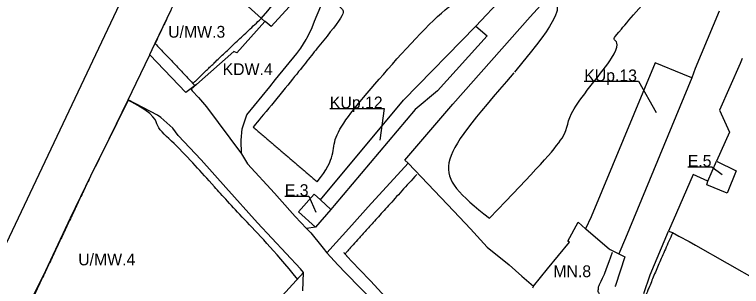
# Model space of a CAD drawing. Extents: x 7424788 to 7425732, y 5549810 to 5550591.
# Drawn here: x 7425037.8 to 7425283.7, y 5550184.4 to 5550276.4 of the extents above; entities that cross this region are included whole.
import ezdxf

# ---------------------------------------------------------------- set-up
doc = ezdxf.new("R2010")
doc.units = 0
for name, color, linetype in [('WIL_granica obszaru objętego planem', 7, 'Continuous'), ('WIL_linia rozgraniczające tereny o różnym przeznaczeniu lub różnych zasadach zagospodarowania', 7, 'Continuous'), ('WIL_linia rozgraniczające tereny o różnym przeznaczeniu lub różnych zasadach zagospodarowania_OPISY', 7, 'Continuous'), ('WIL_nieprzekraczalne linie zabudowy', 7, 'Continuous')]:
    doc.layers.add(name, color=color, linetype=linetype)

msp = doc.modelspace()

# ---------------------------------------------------------------- linework, layer by layer
at = {"layer": 'WIL_granica obszaru objętego planem'}
msp.add_line((7424904.13, 5549923.06), (7425177.26, 5550499.06), dxfattribs=at)
at = {"layer": 'WIL_linia rozgraniczające tereny o różnym przeznaczeniu lub różnych zasadach zagospodarowania'}
for p, q in [((7424904.13, 5549923.06), (7425177.26, 5550499.06)), ((7425098.81, 5550295.36), (7425122.45, 5550274.11)), ((7425207.15, 5550286.68), (7425193.88, 5550272.5)), ((7425212.23, 5550275.61), (7425222.6, 5550287.16)), ((7425139.33, 5550274.15), (7425143.17, 5550283.36)), ((7425131.92, 5550280.39), (7425124.63, 5550272.37)), ((7425085.37, 5550266.74), (7425090.81, 5550278.06)), ((7425186.06, 5550246.06), (7425212.23, 5550275.61)), ((7425276.2, 5550277.52), (7425268.06, 5550258.13)), ((7425122.45, 5550274.11), (7425112.96, 5550263.43)), ((7425122.55, 5550274.02), (7425122.45, 5550274.11)), ((7425124.63, 5550272.37), (7425122.55, 5550274.02)), ((7425138.53, 5550272), (7425139.33, 5550274.15)), ((7425137.5, 5550269.94), (7425138.53, 5550272)), ((7425169.4, 5550247.49), (7425193.88, 5550272.5)), ((7425193.88, 5550272.5), (7425197.67, 5550269.22)), ((7425136.49, 5550268.02), (7425136.73, 5550268.48)), ((7425136.73, 5550268.48), (7425137.5, 5550269.94)), ((7425197.67, 5550269.22), (7425180.93, 5550250.6)), ((7425084.35, 5550264.57), (7425085.37, 5550266.74)), ((7425134.67, 5550265.1), (7425136.49, 5550268.02)), ((7425083.55, 5550262.87), (7425084.35, 5550264.57)), ((7425112, 5550263.95), (7425099.35, 5550252.8)), ((7425112.96, 5550263.43), (7425112, 5550263.95)), ((7425126.12, 5550254.43), (7425133.32, 5550263.28)), ((7425133.32, 5550263.28), (7425134.67, 5550265.1)), ((7425078.96, 5550253.17), (7425083.53, 5550262.83)), ((7425083.53, 5550262.83), (7425083.55, 5550262.87)), ((7425095.8, 5550250.1), (7425083.53, 5550262.83)), ((7425283.97, 5550261.56), (7425283.22, 5550259.84)), ((7425254.57, 5550260.03), (7425232.9, 5550208.02)), ((7425263.83, 5550256.24), (7425254.57, 5550260.03)), ((7425283.22, 5550259.84), (7425276.33, 5550244.06)), ((7425266.93, 5550255.04), (7425263.83, 5550256.24)), ((7425268.06, 5550258.13), (7425266.93, 5550255.04)), ((7425124.16, 5550251.97), (7425126.12, 5550254.43)), ((7425266.93, 5550255.04), (7425244.43, 5550200.77)), ((7425076.29, 5550247.54), (7425078.96, 5550253.17)), ((7425099.35, 5550252.8), (7425095.8, 5550250.1)), ((7425099.35, 5550252.8), (7425097.5, 5550251.18)), ((7425097.5, 5550251.18), (7425097.89, 5550250.66)), ((7425116.4, 5550242.44), (7425124.16, 5550251.97)), ((7425097.89, 5550250.66), (7425100.07, 5550248.32)), ((7425180.93, 5550250.6), (7425173.38, 5550244.35)), ((7425070.29, 5550235.33), (7425076.29, 5550247.54)), ((7425086.15, 5550242.34), (7425076.29, 5550247.54)), ((7425100.07, 5550248.32), (7425102.77, 5550245.19)), ((7425141.27, 5550213.74), (7425169.4, 5550247.49)), ((7425169.89, 5550227.21), (7425186.06, 5550246.06)), ((7425102.77, 5550245.19), (7425114.57, 5550229.26)), ((7425173.38, 5550244.35), (7425145.91, 5550211.81)), ((7425276.33, 5550244.06), (7425279.7, 5550236.65)), ((7425087.31, 5550241.55), (7425086.15, 5550242.34)), ((7425091.4, 5550237.96), (7425087.31, 5550241.55)), ((7425114.85, 5550237.79), (7425116.4, 5550242.44)), ((7425093.12, 5550235.5), (7425091.4, 5550237.96)), ((7425114.43, 5550233.96), (7425114.85, 5550237.79)), ((7425279.7, 5550236.65), (7425275.3, 5550226.79)), ((7425063.61, 5550221.83), (7425070.29, 5550235.33)), ((7425100.91, 5550227.29), (7425093.12, 5550235.5)), ((7425114.57, 5550229.26), (7425114.43, 5550233.96)), ((7425114.57, 5550229.26), (7425116.63, 5550225.93)), ((7425109.28, 5550217.86), (7425100.91, 5550227.29)), ((7425170.93, 5550226.16), (7425169.89, 5550227.21)), ((7425272.35, 5550220.04), (7425275.3, 5550226.79)), ((7425275.3, 5550226.79), (7425281.93, 5550223.6)), ((7425116.63, 5550225.93), (7425125.76, 5550215.95)), ((7425157.45, 5550211.34), (7425170.93, 5550226.16)), ((7425170.93, 5550226.16), (7425173.25, 5550223.73)), ((7425056.69, 5550207.65), (7425063.61, 5550221.83)), ((7425173.25, 5550223.73), (7425186.39, 5550209.91)), ((7425267.41, 5550222.26), (7425261.72, 5550209.31)), ((7425272.35, 5550220.04), (7425267.41, 5550222.26)), ((7425281.93, 5550223.6), (7425278.86, 5550215.96)), ((7425272, 5550218.8), (7425272.35, 5550220.04)), ((7425119.99, 5550206), (7425109.28, 5550217.86)), ((7425278.86, 5550215.96), (7425272, 5550218.8)), ((7425125.76, 5550215.95), (7425127.48, 5550214.08)), ((7425127.48, 5550214.08), (7425132.77, 5550208.11)), ((7425133.82, 5550209.65), (7425139.14, 5550215.71)), ((7425139.14, 5550215.71), (7425141.27, 5550213.74)), ((7425141.27, 5550213.74), (7425144.83, 5550210.45)), ((7425145.91, 5550211.81), (7425144.83, 5550210.45)), ((7425139.56, 5550204.5), (7425133.82, 5550209.65)), ((7425144.83, 5550210.45), (7425139.56, 5550204.5)), ((7425151.95, 5550205.16), (7425157.45, 5550211.34)), ((7425186.39, 5550209.91), (7425192.1, 5550203.98)), ((7425261.72, 5550209.31), (7425259.03, 5550203.19)), ((7425048.44, 5550189.85), (7425056.69, 5550207.65)), ((7425132.77, 5550208.11), (7425136.57, 5550204.08)), ((7425232.9, 5550208.02), (7425231, 5550203.98)), ((7425134.56, 5550190.36), (7425119.99, 5550206)), ((7425139.56, 5550204.5), (7425136.57, 5550204.08)), ((7425143.48, 5550195.76), (7425151.95, 5550205.16)), ((7425224.99, 5550199.72), (7425228.42, 5550206.21)), ((7425228.42, 5550206.21), (7425231, 5550203.98)), ((7425136.57, 5550204.08), (7425138.04, 5550202.52)), ((7425138.04, 5550202.52), (7425139.41, 5550200.83)), ((7425192.1, 5550203.98), (7425197.68, 5550197.68)), ((7425231, 5550203.98), (7425231.16, 5550203.84)), ((7425231.16, 5550203.84), (7425238.93, 5550197.13)), ((7425252.87, 5550188.4), (7425259.03, 5550203.19)), ((7425259.03, 5550203.19), (7425260.41, 5550202.68)), ((7425260.41, 5550202.68), (7425262.56, 5550201.5)), ((7425139.41, 5550200.83), (7425140.39, 5550199.61)), ((7425140.39, 5550199.61), (7425142.22, 5550197.34)), ((7425218.1, 5550190.41), (7425225.55, 5550199.42)), ((7425225.55, 5550199.42), (7425224.99, 5550199.72)), ((7425244.43, 5550200.77), (7425242.23, 5550195.47)), ((7425262.56, 5550201.5), (7425266.02, 5550199.6)), ((7425266.02, 5550199.6), (7425268.19, 5550198.41)), ((7425142.22, 5550197.34), (7425143.48, 5550195.76)), ((7425197.68, 5550197.68), (7425205.12, 5550191.74)), ((7425238.93, 5550197.13), (7425239.3, 5550196.94)), ((7425239.3, 5550196.94), (7425242.23, 5550195.47)), ((7425268.19, 5550198.41), (7425291.09, 5550185.38)), ((7425147.25, 5550191.66), (7425143.48, 5550195.76)), ((7425244.29, 5550194.44), (7425241.1, 5550184.72)), ((7425242.23, 5550195.47), (7425244.29, 5550194.44)), ((7425044.09, 5550181.16), (7425048.44, 5550189.85)), ((7425135.52, 5550189.18), (7425134.56, 5550190.36)), ((7425149.73, 5550189.09), (7425147.25, 5550191.66)), ((7425205.12, 5550191.74), (7425209.45, 5550187.89)), ((7425213.33, 5550184.48), (7425218.1, 5550190.41)), ((7425135.52, 5550189.18), (7425122.11, 5550174.46)), ((7425135.34, 5550182.92), (7425135.52, 5550189.18)), ((7425163.53, 5550175.09), (7425149.73, 5550189.09)), ((7425209.45, 5550187.89), (7425213.33, 5550184.48)), ((7425250.74, 5550182.05), (7425252.87, 5550188.4)), ((7425213.33, 5550184.48), (7425213, 5550183.82)), ((7425241.1, 5550184.72), (7425240.93, 5550184.38))]:
    msp.add_line(p, q, dxfattribs=at)
at = {"layer": 'WIL_linia rozgraniczające tereny o różnym przeznaczeniu lub różnych zasadach zagospodarowania_OPISY'}
for points in [[(7425230.52, 5550253.83), (7425248.9, 5550253.83), (7425254.87, 5550243.27)], [(7425144.47, 5550244.67), (7425162.81, 5550244.67), (7425161.36, 5550233.91)], [(7425265.55, 5550224.94), (7425273.72, 5550224.94), (7425277.14, 5550222.31)], [(7425129.23, 5550215.01), (7425137.36, 5550215.01), (7425139.7, 5550209.52)]]:
    msp.add_lwpolyline(points, dxfattribs=at)
at = {"layer": 'WIL_nieprzekraczalne linie zabudowy'}
for points, degree in [([(7425198.43, 5550207.48), (7425214.24, 5550223.9), (7425226.81, 5550237.4), (7425222.97, 5550241.17), (7425243.74, 5550265.11), (7425240.43, 5550268.16), (7425240.3, 5550268.42), (7425256.84, 5550287.34), (7425277.61, 5550312.54), (7425279.73, 5550311.22), (7425289.78, 5550323.65), (7425286.52, 5550326.6), (7425303.41, 5550346.01), (7425314.85, 5550359.25), (7425313.06, 5550361.03), (7425321.13, 5550371.48), (7425305.65, 5550384.84), (7425294.14, 5550370.95), (7425269.41, 5550342.11), (7425267.03, 5550339.06), (7425265.3, 5550337.01), (7425268.22, 5550334.57), (7425251.81, 5550317.24), (7425232.23, 5550295.28), (7425230.78, 5550292.96), (7425222.05, 5550283.57), (7425219.8, 5550280.13), (7425223.37, 5550276.56), (7425206.92, 5550256.89)], 3), ([(7425140.2, 5550219.85), (7425146.9, 5550228.14), (7425142.94, 5550232.9), (7425158.81, 5550252.21), (7425188.63, 5550285.42), (7425194.4, 5550279.73), (7425203.66, 5550289.65), (7425178.12, 5550312.94), (7425165.03, 5550300.63), (7425159.87, 5550304.6), (7425158.81, 5550305.13), (7425149.95, 5550294.28), (7425149.02, 5550293.23), (7425152.46, 5550289.65), (7425145.32, 5550281.19), (7425148.49, 5550278.41), (7425150.08, 5550277.09), (7425139.5, 5550264.25), (7425133.28, 5550256.18), (7425120.18, 5550240.31), (7425118.49, 5550238.35)], 3), ([(7425121.21, 5550275.03), (7425134.5, 5550289.72), (7425124.58, 5550298.69), (7425121.07, 5550301.98), (7425119.26, 5550299.82)], 3), ([(7425098.84, 5550295.15), (7425085.37, 5550266.65)], 1), ([(7425098.08, 5550253.07), (7425107.05, 5550261.76), (7425121.21, 5550275.03)], 2), ([(7425085.37, 5550266.65), (7425098.88, 5550252.32)], 1), ([(7425206.73, 5550256.69), (7425179.32, 5550224.96), (7425178.26, 5550223.77), (7425198.43, 5550207.48)], 3), ([(7425076.25, 5550247.42), (7425063.48, 5550221.69)], 1), ([(7425076.25, 5550247.42), (7425076.27, 5550247.41)], 1), ([(7425133.61, 5550186.84), (7425125.39, 5550196.96), (7425114.54, 5550207.96), (7425104.72, 5550218.96), (7425099.29, 5550224.97), (7425091.67, 5550233.18), (7425084.77, 5550238.9), (7425086.09, 5550242.27), (7425076.25, 5550247.42)], 3), ([(7425118.49, 5550238.35), (7425140.2, 5550219.85)], 1), ([(7425063.48, 5550221.69), (7425044.62, 5550181.81)], 1), ([(7425173.89, 5550222.32), (7425151.01, 5550197.18), (7425149.61, 5550195.4)], 2), ([(7425260.39, 5550202.49), (7425252.71, 5550185.44), (7425249.46, 5550176.31)], 2), ([(7425149.15, 5550195.88), (7425149.61, 5550195.4)], 1), ([(7425149.61, 5550195.4), (7425150.13, 5550194.84)], 1), ([(7425150.13, 5550194.84), (7425173.71, 5550169.9), (7425192.97, 5550150.03), (7425193.22, 5550148.26), (7425196.28, 5550146.1), (7425200.58, 5550141.39), (7425206.26, 5550135.89), (7425210.31, 5550131.77)], 3), ([(7425229.43, 5550170.39), (7425234.03, 5550180.16), (7425234.68, 5550180.2), (7425234.98, 5550180.28), (7425235.75, 5550181.41), (7425235.7, 5550182.14), (7425235, 5550182.73), (7425235.55, 5550183.56), (7425234.96, 5550184.24), (7425236.88, 5550186.76), (7425240.12, 5550196.02)], 3)]:
    msp.add_open_spline(points, degree=degree, dxfattribs=at)

# ---------------------------------------------------------------- texts
at = {"layer": 'WIL_linia rozgraniczające tereny o różnym przeznaczeniu lub różnych zasadach zagospodarowania_OPISY'}
for s, p in [('U/MW.3', (7425089.77, 5550268.59)), ('KDW.4', (7425108.19, 5550255.93)), ('KUp.13', (7425230.52, 5550253.83)), ('KUp.12', (7425144.47, 5550244.67)), ('E.5', (7425265.55, 5550224.94)), ('E.3', (7425129.23, 5550215.01)), ('U/MW.4', (7425059.35, 5550191.57)), ('MN.8', (7425220.07, 5550187.57))]:
    msp.add_text(s, height=4, dxfattribs=at).set_placement(p)

doc.saveas('drawing.dxf')
